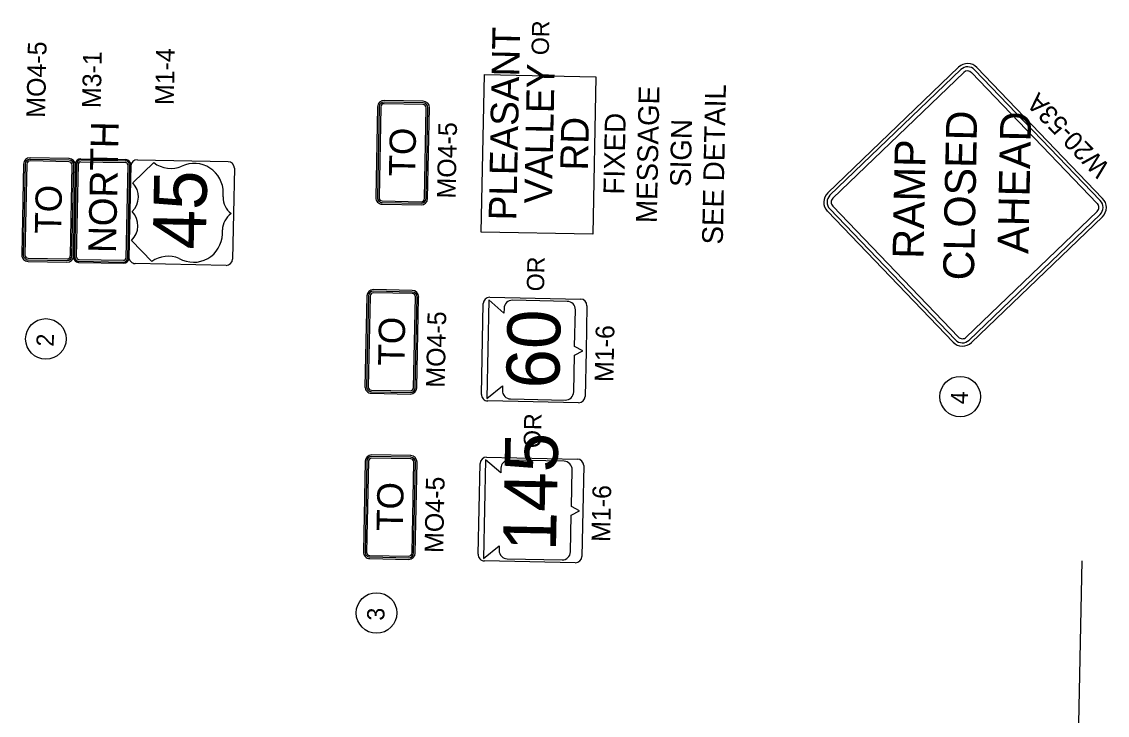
# Model space of a CAD drawing. Extents: x 345549 to 379569, y 127949 to 230467.
# Drawn here: x 353642 to 363059, y 217351 to 223369 of the extents above; entities that cross this region are included whole.
import ezdxf

# ---------------------------------------------------------------- set-up
doc = ezdxf.new("R2010")
doc.units = 0
doc.layers.add('CA-TEXT', color=7, linetype='Continuous')
doc.layers.add('P_SGN_Cell', color=7, linetype='Continuous')

msp = doc.modelspace()

# ---------------------------------------------------------------- linework, layer by layer
at = {"layer": 'CA-TEXT'}
msp.add_line((362083.9, 181042.3), (362842.1, 218691.5), dxfattribs=at)
for centre in [(353851.7, 220616.4), (361782.9, 220115.8), (356719.9, 218238.4)]:
    msp.add_circle(centre, 175.9, dxfattribs=at)
at = {"layer": 'P_SGN_Cell'}
for p, q in [((354153.6, 222169), (354543.5, 222161.2)), ((354153.9, 222180.3), (354543.8, 222172.4)), ((354645, 222170.4), (355432.3, 222154.6)), ((354091.6, 221325.8), (354108, 222136.2)), ((354102.9, 221326.1), (354119.2, 222136)), ((354117.9, 221325.8), (354134.2, 222135.7)), ((354153.3, 222154), (354543.2, 222146.2)), ((354561.6, 222127.1), (354545.3, 221317.2)), ((354576.6, 222126.8), (354560.3, 221316.9)), ((354587.9, 222126.5), (354571.6, 221316.7)), ((354571.8, 221327.9), (354587.6, 222115.3)), ((354787.8, 222146.1), (354605.7, 221971.2)), ((355487.5, 222097.2), (355479.5, 221703.5)), ((355487.4, 222097.2), (355487.5, 222097.2)), ((355389.2, 221848.2), (355389.9, 221883.9)), ((355479.5, 221703.5), (355471.6, 221309.8)), ((355382.7, 221526.8), (355383.4, 221562.5)), ((354595.6, 221471.2), (354770.6, 221289.1)), ((354136.3, 221306.7), (354526.2, 221298.9)), ((354135.7, 221280.5), (354525.7, 221272.6)), ((354136, 221291.7), (354525.9, 221283.9)), ((355414.2, 221254.7), (354626.9, 221270.6)), ((357693.3, 220956.3), (357676, 220100.2)), ((357825.3, 220841.1), (357693.3, 220956.3)), ((357703.1, 220978), (358490.4, 220962.2)), ((358374.4, 220942.6), (357899.5, 220952.2)), ((357629.8, 220135.6), (357645.7, 220922.9)), ((357826.2, 220881.8), (357825.3, 220841.1)), ((358438.4, 220550.6), (358444.8, 220869.3)), ((358545.5, 220904.8), (358537.6, 220511.1)), ((358430.4, 220156.9), (358436.8, 220475.6)), ((358436.8, 220475.6), (358509.5, 220511.7)), ((358509.5, 220511.7), (358438.4, 220550.6)), ((358537.6, 220511.1), (358529.7, 220117.4)), ((357676, 220100.2), (357812.6, 220210)), ((357812.6, 220210), (357811.8, 220169.4)), ((357882.2, 220096.1), (358357.1, 220086.5)), ((358472.3, 220062.3), (357684.9, 220078.2)), ((357601.9, 218747.8), (357617.7, 219535.1)), ((357665.3, 219568.6), (357648.1, 218712.5)), ((357797.4, 219453.4), (357665.3, 219568.6)), ((357675.1, 219590.3), (358462.4, 219574.4)), ((358346.4, 219554.8), (357871.5, 219564.4)), ((357798.2, 219494), (357797.4, 219453.4)), ((358410.4, 219162.9), (358416.8, 219481.5)), ((358517.6, 219517), (358509.6, 219123.4)), ((358481.5, 219123.9), (358410.4, 219162.9)), ((358402.5, 218769.2), (358408.9, 219087.9)), ((358408.9, 219087.9), (358481.5, 219123.9)), ((358509.6, 219123.4), (358501.7, 218729.7)), ((357648.1, 218712.5), (357784.7, 218822.3)), ((357784.7, 218822.3), (357783.8, 218781.6)), ((358444.3, 218674.6), (357657, 218690.4)), ((357854.3, 218708.3), (358329.2, 218698.8))]:
    msp.add_line(p, q, dxfattribs=at)
msp.add_lwpolyline([(357629.1, 221543.7), (357656.6, 222910.8), (358623.8, 222891.3), (358596.3, 221524.2)], close=True, dxfattribs=at)
for points in [[(361769.8, 222974.5), (360633.9, 221883.4)], [(361789.6, 222953.9), (360653.7, 221862.8)], [(361814.3, 222928.1), (360678.4, 221837.1)], [(362972.6, 221791.7), (361882, 222927.2)], [(362998.4, 221816.5), (361907.8, 222952)], [(363019, 221836.3), (361928.3, 222971.8)], [(356729.3, 222630.5), (356713.4, 221843.2)], [(356743.3, 222630.3), (356727.5, 221842.9)], [(356757.4, 222630), (356741.6, 221842.6)], [(357123.5, 222650.7), (356786.1, 222657.5)], [(357123.8, 222664.8), (356786.4, 222671.6)], [(357124.1, 222678.8), (356786.6, 222685.6)], [(357135.2, 221834.7), (357151.1, 222622)], [(357149.3, 221834.4), (357165.1, 222621.8)], [(357163.3, 221834.1), (357179.2, 222621.5)], [(354052.1, 222153.9), (353714.6, 222160.7)], [(354052.3, 222168), (353714.9, 222174.7)], [(354052.6, 222182), (353715.2, 222188.8)], [(353657.8, 222133.7), (353642, 221346.4)], [(353671.9, 222133.4), (353656, 221346.1)], [(353686, 222133.1), (353670.1, 221345.8)], [(354063.8, 221337.9), (354079.6, 222125.2)], [(354077.8, 221337.6), (354093.7, 222124.9)], [(354091.9, 221337.3), (354107.7, 222124.6)], [(356768.5, 221785.8), (357106, 221779)], [(356768.8, 221799.9), (357106.2, 221793.1)], [(356769.1, 221813.9), (357106.5, 221807.1)], [(360630.7, 221724.4), (361721.7, 220588.5)], [(360651.3, 221744.1), (361742.3, 220608.3)], [(360677.1, 221768.9), (361768.1, 220633)], [(361836.3, 220631.6), (362972.2, 221722.7)], [(361861, 220605.9), (362996.9, 221696.9)], [(361880.8, 220585.3), (363016.7, 221676.3)], [(353697.6, 221317.1), (354035.1, 221310.3)], [(353697.1, 221289), (354034.5, 221282.2)], [(353697.3, 221303), (354034.8, 221296.3)], [(357030.1, 221023.5), (356692.7, 221030.3)], [(357030.4, 221037.6), (356693, 221044.4)], [(356635.6, 220989.3), (356619.8, 220201.9)], [(356649.7, 220989), (356633.8, 220201.7)], [(356663.7, 220988.7), (356647.9, 220201.4)], [(357029.9, 221009.5), (356692.4, 221016.3)], [(357041.6, 220193.4), (357057.4, 220980.8)], [(357055.6, 220193.2), (357071.5, 220980.5)], [(357069.7, 220192.9), (357085.5, 220980.2)], [(356674.9, 220144.6), (357012.3, 220137.8)], [(356675.1, 220158.6), (357012.6, 220151.8)], [(356675.4, 220172.7), (357012.9, 220165.9)], [(356621.9, 219555.3), (356606, 218767.9)], [(356636, 219555), (356620.1, 218767.6)], [(356650, 219554.7), (356634.2, 218767.3)], [(357016.1, 219575.4), (356678.7, 219582.2)], [(357016.4, 219589.5), (356679, 219596.3)], [(357016.7, 219603.6), (356679.3, 219610.4)], [(357027.8, 218759.4), (357043.7, 219546.8)], [(357041.9, 218759.1), (357057.7, 219546.5)], [(357055.9, 218758.9), (357071.8, 219546.2)], [(356661.1, 218710.5), (356998.6, 218703.7)], [(356661.4, 218724.6), (356998.8, 218717.8)], [(356661.7, 218738.7), (356999.1, 218731.9)]]:
    msp.add_lwpolyline(points, dxfattribs=at)
for centre, radius, start, end in [((361847.7, 222893.3), 112.5, 43.84622, 133.84622), ((361847.7, 222893.3), 83.9, 43.84622, 133.84622), ((361847.7, 222893.3), 48.2, 43.84622, 133.84622), ((356785.5, 222629.4), 56.3, 88.84622, 178.84622), ((356785.5, 222629.4), 42.2, 88.84622, 178.84622), ((356785.5, 222629.4), 28.1, 88.84622, 178.84622), ((357123, 222622.6), 28.1, 358.84622, 88.84622), ((357123, 222622.6), 42.2, 358.84622, 88.84622), ((357123, 222622.6), 56.3, 358.84622, 88.84622), ((353714.1, 222132.6), 56.3, 88.84622, 178.84622), ((353714.1, 222132.6), 42.2, 88.84622, 178.84622), ((353714.1, 222132.6), 28.1, 88.84622, 178.84622), ((354051.5, 222125.8), 42.2, 358.84622, 88.84622), ((354051.5, 222125.8), 56.3, 358.84622, 88.84622), ((354153, 222135.3), 45, 88.84622, 178.84622), ((354153, 222135.3), 33.7, 88.84622, 178.84622), ((354542.9, 222127.4), 33.7, 358.84622, 88.84622), ((354542.9, 222127.4), 45, 358.84622, 88.84622), ((354643.9, 222114.2), 56.2, 88.84622, 178.84622), ((355431.2, 222098.3), 56.2, 358.84622, 88.84622), ((354051.5, 222125.8), 28.1, 358.84622, 88.84622), ((354153, 222135.3), 18.7, 88.84622, 178.84622), ((354542.9, 222127.4), 18.7, 358.84622, 88.84622), ((354937.9, 222346.1), 250, 233.11428, 291.9873), ((355139.9, 221889), 250, 358.84616, 115.69277), ((354475.7, 221848.8), 178.6, 314.41906, 43.27339), ((360711.8, 221802.3), 112.5, 133.84433, 223.84622), ((355569.9, 221845.7), 180.8, 179.18852, 231.63404), ((356769.7, 221842.1), 56.3, 178.84622, 268.84622), ((356769.7, 221842.1), 42.2, 178.84622, 268.84622), ((356769.7, 221842.1), 28.1, 178.84622, 268.84622), ((357107.1, 221835.3), 56.3, 268.84622, 358.84622), ((357107.1, 221835.3), 42.2, 268.84622, 358.84622), ((357107.1, 221835.3), 28.1, 268.84622, 358.84622), ((360711.8, 221802.3), 83.9, 133.84433, 223.84622), ((360711.8, 221802.3), 48.2, 133.84433, 223.84622), ((362938.7, 221757.4), 48.2, 313.85344, 44.49709), ((362938.7, 221757.4), 83.9, 313.85344, 44.49709), ((362938.7, 221757.4), 112.5, 313.85344, 44.49709), ((354470.6, 221598.8), 178.6, 314.41906, 43.27339), ((355564.1, 221557.8), 180.8, 126.05841, 178.50393), ((355132.7, 221531.8), 250, 240.09813, 358.84629), ((353698.2, 221345.2), 56.3, 178.84622, 268.84622), ((353698.2, 221345.2), 42.2, 178.84622, 268.84622), ((353698.2, 221345.2), 28.1, 178.84622, 268.84622), ((354035.6, 221338.4), 56.3, 268.84622, 358.84622), ((354035.6, 221338.4), 42.2, 268.84622, 358.84622), ((354035.6, 221338.4), 28.1, 268.84622, 358.84622), ((354136.6, 221325.5), 45, 179.61188, 268.84622), ((354136.6, 221325.5), 33.7, 178.84622, 268.84622), ((354136.6, 221325.5), 18.7, 178.84622, 268.84622), ((354526.6, 221317.6), 45, 268.84622, 358.84622), ((354526.6, 221317.6), 33.7, 268.84622, 358.84622), ((354526.6, 221317.6), 18.7, 268.84622, 358.84622), ((354628, 221326.8), 56.2, 178.84622, 268.84622), ((354913.3, 221083.7), 250, 67.71592, 124.79823), ((355415.4, 221311), 56.2, 268.84622, 358.84622), ((356691.9, 220988.1), 56.3, 88.84622, 178.84622), ((356691.9, 220988.1), 42.2, 88.84622, 178.84622), ((357029.3, 220981.3), 56.3, 358.84622, 88.84622), ((356691.9, 220988.1), 28.1, 88.84622, 178.84622), ((357029.3, 220981.3), 28.1, 358.84622, 88.84622), ((357029.3, 220981.3), 42.2, 358.84622, 88.84622), ((357701.9, 220921.8), 56.2, 88.84622, 178.84622), ((357898, 220880.3), 71.9, 88.84622, 178.84622), ((358372.9, 220870.7), 71.9, 358.84622, 88.84622), ((358489.3, 220905.9), 56.2, 358.84622, 88.84622), ((361802.8, 220666.4), 112.5, 223.84622, 313.84622), ((361802.8, 220666.4), 83.9, 223.84622, 313.84622), ((361802.8, 220666.4), 48.2, 223.84622, 313.84622), ((356676, 220200.8), 56.3, 178.84622, 268.84622), ((356676, 220200.8), 42.2, 178.84622, 268.84622), ((356676, 220200.8), 28.1, 178.84622, 268.84622), ((357013.4, 220194), 56.3, 268.84622, 358.84622), ((357013.4, 220194), 42.2, 268.84622, 358.84622), ((357013.4, 220194), 28.1, 268.84622, 358.84622), ((357686.1, 220134.4), 56.2, 178.84622, 268.84622), ((357883.7, 220168), 71.9, 178.84622, 268.84622), ((358358.6, 220158.4), 71.9, 268.84622, 358.84622), ((358473.4, 220118.6), 56.2, 268.84622, 358.84622), ((356678.1, 219554.1), 56.3, 88.84622, 178.84622), ((356678.1, 219554.1), 42.2, 88.84622, 178.84622), ((356678.1, 219554.1), 28.1, 88.84622, 178.84622), ((357015.6, 219547.3), 28.1, 358.84622, 88.84622), ((357015.6, 219547.3), 42.2, 358.84622, 88.84622), ((357015.6, 219547.3), 56.3, 358.84622, 88.84622), ((357674, 219534), 56.2, 88.84622, 178.84622), ((357870.1, 219492.6), 71.9, 88.84622, 178.84622), ((358345, 219483), 71.9, 358.84622, 88.84622), ((358461.3, 219518.2), 56.2, 358.84622, 88.84622), ((356662.3, 218766.8), 56.3, 178.84622, 268.84622), ((356662.3, 218766.8), 42.2, 178.84622, 268.84622), ((356662.3, 218766.8), 28.1, 178.84622, 268.84622), ((357855.7, 218780.2), 71.9, 178.84622, 268.84622), ((358330.6, 218770.6), 71.9, 268.84622, 358.84622), ((356999.7, 218760), 56.3, 268.84622, 358.84622), ((356999.7, 218760), 42.2, 268.84622, 358.84622), ((356999.7, 218760), 28.1, 268.84622, 358.84622), ((357658.1, 218746.7), 56.2, 178.84622, 268.84622), ((358445.5, 218730.8), 56.2, 268.84622, 358.84622)]:
    msp.add_arc(centre, radius, start, end, dxfattribs=at)

# ---------------------------------------------------------------- texts
at = {"layer": 'CA-TEXT'}
for s, p in [('OR', (358214.2, 223077.4)), ('OR', (358172.9, 221028.5)), ('2', (353919.3, 220548.9)), ('4', (361850.6, 220048.2)), ('OR', (358145.5, 219668.5)), ('3', (356787.6, 218170.9))]:
    msp.add_text(s, height=150, rotation=88.84682, dxfattribs=at).set_placement(p)
at = {"layer": 'P_SGN_Cell'}
for s, height, rotation, p in [('PLEASANT', 240, 88.84622, (357932.3, 221643.1)), ('MO4-5', 162, 88.84622, (353844.7, 222534)), ('M3-1', 162, 88.84622, (354327.4, 222618)), ('M1-4', 162, 88.84622, (354960.7, 222644.2)), ('VALLEY', 240, 88.84622, (358241.5, 221789.1)), ('SEE DETAIL', 180, 88.84622, (359723.4, 221434.4)), ('MESSAGE', 180, 88.84622, (359151, 221620.3)), ('W20-53A', 162, 133.84622, (363090.3, 222111.9)), ('FIXED', 180, 88.84622, (358867.9, 221867.7)), ('CLOSED', 267.86, 88.84622, (361901.6, 221122.6)), ('AHEAD', 267.86, 88.84622, (362374.8, 221353)), ('NORTH', 240, 88.84622, (354459.8, 221360.1)), ('MO4-5', 162, 88.84622, (357405.4, 221833.2)), ('RD', 240, 88.84622, (358553.4, 222076.5)), ('SIGN', 180, 88.84622, (359445.4, 221934)), ('TO', 228, 88.84622, (357054.9, 222023.7)), ('RAMP', 267.86, 88.84622, (361464.1, 221309.6)), ('45', 460, 88.84622, (355237.6, 221390)), ('TO', 228, 88.84622, (353983.4, 221526.9)), ('MO4-5', 162, 88.84622, (357311.7, 220192)), ('60', 460, 88.84622, (358304.4, 220182.7)), ('TO', 228, 88.84622, (356961.2, 220382.5)), ('M1-6', 162, 88.84622, (358774.2, 220241.2)), ('145', 460, 88.84622, (358276, 218771.9)), ('TO', 228, 88.84622, (356947.5, 218948.4)), ('MO4-5', 162, 88.84622, (357298, 218757.9)), ('M1-6', 162, 88.84622, (358746.3, 218853.5))]:
    msp.add_text(s, height=height, rotation=rotation, dxfattribs=at).set_placement(p)

doc.saveas('drawing.dxf')
